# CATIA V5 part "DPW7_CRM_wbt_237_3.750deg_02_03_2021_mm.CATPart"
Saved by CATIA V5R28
Part number: DPW7_CRM_wbt_237_3.750deg_02_03_2021
Bounding box of the stored display mesh (mm): x 2349.5 to 66711.891, y 0 to 29552.9, z 2310.119 to 8715.756
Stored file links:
  Z:\Scratch\04_CAD_Allgemein\Flight2Jig\Output\DPW-7\CATPart\DPW7_CRM_wbt_182_3.750deg_02_03_2021.CATPart
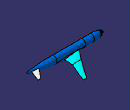
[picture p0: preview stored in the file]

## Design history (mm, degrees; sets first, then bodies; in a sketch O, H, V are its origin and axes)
Set1
  DatumSurface1 "Clean_Wing"
  DatumSurface2 "Fuselage"
  DatumSurface3 "HTP"
  DatumSurface4 "Symmetry"
  DatumSurface5 "Farfield"
Body1 (main body)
